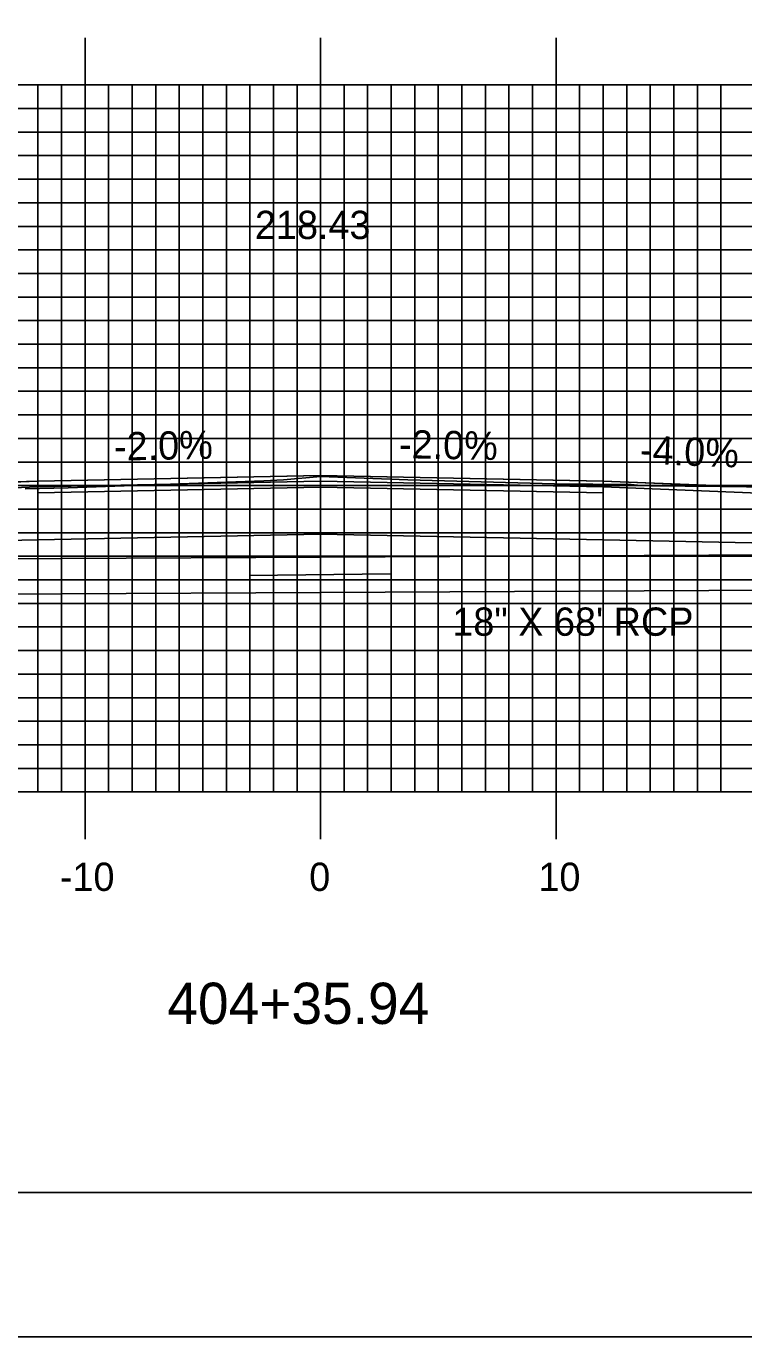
# Model space of a CAD drawing. Extents: x 851348 to 851692, y 364785 to 365005.
# Drawn here: x 851501.7 to 851532.2, y 364785.1 to 364840.7 of the extents above; entities that cross this region are included whole.
import ezdxf

# ---------------------------------------------------------------- set-up
doc = ezdxf.new("R2010")
doc.units = 0
for name, color, linetype in [('ANNOTATION', 7, 'Continuous'), ('BORDER', 7, 'Continuous'), ('D_Drainage_Culvert', 7, 'Continuous'), ('D_Drainage_Text', 7, 'Continuous'), ('D_Roadway_Centerline', 7, 'Continuous'), ('D_Roadway_Centerline_Text', 7, 'Continuous'), ('D_Roadway_Edge_Shoulder', 7, 'Continuous'), ('D_Roadway_Edge_TW', 7, 'Continuous'), ('D_Roadway_Pavement', 7, 'Continuous'), ('D_Roadway_SubGrade', 7, 'Continuous'), ('H_V ANNOTATION', 7, 'Continuous'), ('MAJOR', 7, 'Continuous'), ('MINOR', 7, 'Continuous'), ('PLOT BOUNDARY', 7, 'Continuous'), ('S_Roadway_Centerline', 7, 'Continuous')]:
    doc.layers.add(name, color=color, linetype=linetype)

msp = doc.modelspace()

# ---------------------------------------------------------------- linework, layer by layer
at = {"layer": 'BORDER'}
msp.add_lwpolyline([(851364.591, 364791.233), (851684.591, 364791.233), (851684.591, 365001.233), (851364.591, 365001.233)], close=True, dxfattribs=at)
at = {"layer": 'D_Drainage_Culvert'}
for p, q in [((851480.479, 364818.026), (851548.483, 364818.366)), ((851517.159, 364817.483), (851511.159, 364817.423)), ((851548.49, 364816.866), (851480.463, 364816.525))]:
    msp.add_line(p, q, dxfattribs=at)
at = {"layer": 'D_Roadway_Centerline'}
msp.add_lwpolyline([(851485.104, 364818.833), (851493.575, 364820.951), (851494.191, 364821.105), (851501.707, 364821.405), (851502.191, 364821.425), (851513.465, 364821.65), (851514.191, 364821.665), (851525.465, 364821.439), (851526.191, 364821.425), (851533.707, 364821.124), (851534.191, 364821.105), (851543.731, 364819.245)], dxfattribs=at)
at = {"layer": 'D_Roadway_Edge_Shoulder'}
for points in [[(851502.191, 364821.425), (851494.191, 364821.105), (851494.191, 364820.855), (851502.191, 364821.175)], [(851526.191, 364821.425), (851534.191, 364821.105), (851534.191, 364820.855), (851526.191, 364821.175)]]:
    msp.add_lwpolyline(points, close=True, dxfattribs=at)
at = {"layer": 'D_Roadway_Edge_TW'}
msp.add_lwpolyline([(851502.191, 364821.175), (851502.191, 364821.425), (851514.191, 364821.665), (851526.191, 364821.425), (851526.191, 364821.175), (851514.191, 364821.415)], close=True, dxfattribs=at)
at = {"layer": 'D_Roadway_Pavement'}
msp.add_lwpolyline([(851502.191, 364820.925), (851502.191, 364821.175), (851514.191, 364821.415), (851526.191, 364821.175), (851526.191, 364820.925), (851514.191, 364821.165)], close=True, dxfattribs=at)
at = {"layer": 'D_Roadway_SubGrade'}
msp.add_lwpolyline([(851485.104, 364818.833), (851494.191, 364821.105), (851494.191, 364820.855), (851502.191, 364821.175), (851514.191, 364821.415), (851526.191, 364821.175), (851534.191, 364820.855), (851534.191, 364821.105), (851543.731, 364819.245), (851543.731, 364818.574), (851526.191, 364818.925), (851514.191, 364819.165), (851502.191, 364818.925), (851485.104, 364818.583)], dxfattribs=at)
at = {"layer": 'MAJOR'}
for p, q in [((851504.191, 364840.237), (851504.191, 364838.233)), ((851514.191, 364840.237), (851514.191, 364838.233)), ((851524.191, 364840.237), (851524.191, 364838.233)), ((851374.191, 364838.233), (851654.191, 364838.233)), ((851374.191, 364838.233), (851654.191, 364838.233)), ((851504.191, 364808.233), (851504.191, 364838.233)), ((851514.191, 364808.233), (851514.191, 364838.233)), ((851524.191, 364808.233), (851524.191, 364838.233)), ((851374.191, 364833.233), (851654.191, 364833.233)), ((851374.191, 364828.233), (851654.191, 364828.233)), ((851374.191, 364823.233), (851654.191, 364823.233)), ((851374.191, 364818.233), (851654.191, 364818.233)), ((851374.191, 364813.233), (851654.191, 364813.233)), ((851374.191, 364808.233), (851654.191, 364808.233)), ((851374.191, 364808.233), (851654.191, 364808.233)), ((851504.191, 364806.229), (851504.191, 364808.233)), ((851514.191, 364806.229), (851514.191, 364808.233)), ((851524.191, 364806.229), (851524.191, 364808.233))]:
    msp.add_line(p, q, dxfattribs=at)
at = {"layer": 'MINOR'}
for p, q in [((851502.191, 364808.233), (851502.191, 364838.233)), ((851503.191, 364808.233), (851503.191, 364838.233)), ((851505.191, 364808.233), (851505.191, 364838.233)), ((851506.191, 364808.233), (851506.191, 364838.233)), ((851507.191, 364808.233), (851507.191, 364838.233)), ((851508.191, 364808.233), (851508.191, 364838.233)), ((851509.191, 364808.233), (851509.191, 364838.233)), ((851510.191, 364808.233), (851510.191, 364838.233)), ((851511.191, 364808.233), (851511.191, 364838.233)), ((851512.191, 364808.233), (851512.191, 364838.233)), ((851513.191, 364808.233), (851513.191, 364838.233)), ((851515.191, 364808.233), (851515.191, 364838.233)), ((851516.191, 364808.233), (851516.191, 364838.233)), ((851517.191, 364808.233), (851517.191, 364838.233)), ((851518.191, 364808.233), (851518.191, 364838.233)), ((851519.191, 364808.233), (851519.191, 364838.233)), ((851520.191, 364808.233), (851520.191, 364838.233)), ((851521.191, 364808.233), (851521.191, 364838.233)), ((851522.191, 364808.233), (851522.191, 364838.233)), ((851523.191, 364808.233), (851523.191, 364838.233)), ((851525.191, 364808.233), (851525.191, 364838.233)), ((851526.191, 364808.233), (851526.191, 364838.233)), ((851527.191, 364808.233), (851527.191, 364838.233)), ((851528.191, 364808.233), (851528.191, 364838.233)), ((851529.191, 364808.233), (851529.191, 364838.233)), ((851530.191, 364808.233), (851530.191, 364838.233)), ((851531.191, 364808.233), (851531.191, 364838.233)), ((851374.191, 364837.233), (851654.191, 364837.233)), ((851374.191, 364836.233), (851654.191, 364836.233)), ((851374.191, 364835.233), (851654.191, 364835.233)), ((851374.191, 364834.233), (851654.191, 364834.233)), ((851374.191, 364832.233), (851654.191, 364832.233)), ((851374.191, 364831.233), (851654.191, 364831.233)), ((851374.191, 364830.233), (851654.191, 364830.233)), ((851374.191, 364829.233), (851654.191, 364829.233)), ((851374.191, 364827.233), (851654.191, 364827.233)), ((851374.191, 364826.233), (851654.191, 364826.233)), ((851374.191, 364825.233), (851654.191, 364825.233)), ((851374.191, 364824.233), (851654.191, 364824.233)), ((851374.191, 364822.233), (851654.191, 364822.233)), ((851374.191, 364821.233), (851654.191, 364821.233)), ((851374.191, 364820.233), (851654.191, 364820.233)), ((851374.191, 364819.233), (851654.191, 364819.233)), ((851374.191, 364817.233), (851654.191, 364817.233)), ((851374.191, 364816.233), (851654.191, 364816.233)), ((851374.191, 364815.233), (851654.191, 364815.233)), ((851374.191, 364814.233), (851654.191, 364814.233)), ((851374.191, 364812.233), (851654.191, 364812.233)), ((851374.191, 364811.233), (851654.191, 364811.233)), ((851374.191, 364810.233), (851654.191, 364810.233)), ((851374.191, 364809.233), (851654.191, 364809.233))]:
    msp.add_line(p, q, dxfattribs=at)
at = {"layer": 'PLOT BOUNDARY'}
msp.add_lwpolyline([(851348.405, 364785.114), (851688.405, 364785.114), (851688.405, 365005.114), (851348.405, 365005.114)], close=True, dxfattribs=at)
at = {"layer": 'S_Roadway_Centerline'}
msp.add_lwpolyline([(851501.644, 364821.094), (851503.47, 364821.135), (851511.788, 364821.434), (851512.611, 364821.478), (851514.185, 364821.613), (851517.902, 364821.483), (851524.124, 364821.311), (851527.38, 364821.278), (851527.773, 364821.239), (851528.153, 364821.217), (851532.695, 364821.183)], dxfattribs=at)

# ---------------------------------------------------------------- texts
at = {"layer": 'ANNOTATION'}
for s, rotation, p in [('-2.0%', 1.1458, (851505.434, 364822.29)), ('-2.0%', 358.8542, (851517.514, 364822.399)), ('-4.0%', 357.7094, (851527.741, 364822.164))]:
    msp.add_text(s, height=1.2, rotation=rotation, dxfattribs=at).set_placement(p)
at = {"layer": 'D_Drainage_Text'}
msp.add_text('18" X 68\' RCP', height=1.2, dxfattribs=at).set_placement((851519.786, 364814.86))
at = {"layer": 'D_Roadway_Centerline_Text'}
msp.add_text('218.43', height=1.2, dxfattribs=at).set_placement((851511.404, 364831.695))
at = {"layer": 'H_V ANNOTATION'}
for s, height, p in [('-10', 1.2, (851503.121, 364804.033)), ('0', 1.2, (851513.71, 364804.033)), ('10', 1.2, (851523.442, 364804.033)), ('404+35.94', 1.75, (851507.684, 364798.389))]:
    msp.add_text(s, height=height, dxfattribs=at).set_placement(p)

doc.saveas('drawing.dxf')
